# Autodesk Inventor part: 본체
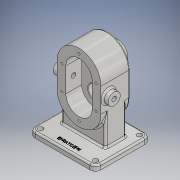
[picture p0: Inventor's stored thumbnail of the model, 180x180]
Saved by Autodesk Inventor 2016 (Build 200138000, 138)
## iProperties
Created: 2020-09
Part Number: 본체
Material: 알루미늄 6061
Document SubType Name: Modeling
Designer: WIN7
Density: 2.7 g/cm^3
Appearance: 알루미늄 - 평지
Mass: 1440.46 g
Surface Area: 785.636 cm^2
Volume: 533.505 cm^3
Author: WIN7
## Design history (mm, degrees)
sketch "스케치1"
  geometry: L1 (0, -62)-(0, -62); L2 (40, -22)-(40, 22); L3 (0, 62)-(0, 62); L4 (-40, 22)-(-40, -22); L5 (-40, -62)-(40, 62); L6 (40, -62)-(-40, 62); A1 r 40 centre (0, 22) between (0, 62) and (-40, 22); A2 r 40 centre (0, 22) between (40, 22) and (0, 62); A3 r 40 centre (0, -22) between (0, -62) and (40, -22); A4 r 40 centre (0, -22) between (-40, -22) and (0, -62); 1 further point
  constraints: 12 end point, 8 point on circle, 8 point on line, 8 tangent, 4 centre point, 3 equal radius, 2 midpoint, 2 parallel, 1 horizontal, 1 perpendicular
  dimensions: "d0" = 80 distance between parallel lines of L2 L4; "d1" = 124 distance between parallel lines of L3 L1; "d2" = 40 radius of A1
extrude "돌출1" new body sketch "스케치1" stored distance "d3" = 53; taper "d4" = 0 deg
sketch "스케치2"
  geometry: L1 (0, 46)-(0, 46); L2 (24, 22)-(24, -22); L3 (0, -46)-(0, -46); L4 (-24, -22)-(-24, 22); L5 (-24, 46)-(24, -46); L6 (24, 46)-(-24, -46); L7 (-40, 22)-(-40, -22) reference; A1 r 40 centre (0, 22) between (40, 22) and (-40, 22) reference; A2 r 24 centre (0, 22) between (0, 46) and (-24, 22); A3 r 24 centre (0, 22) between (24, 22) and (0, 46); A4 r 24 centre (0, -22) between (-24, -22) and (0, -46); A5 r 24 centre (0, -22) between (0, -46) and (24, -22); 6 further points
  constraints: 12 end point, 9 point on circle, 8 point on line, 8 tangent, 5 midpoint, 4 centre point, 3 equal radius, 2 parallel, 1 horizontal, 1 horizontal alignment, 1 perpendicular, 1 vertical alignment
  dimensions: "d5" = 92 distance of L6.start L5.end; "d6" = 48 distance between parallel lines of L2 L4; "d7" = 24 radius of A2
extrude "돌출2" cut sketch "스케치2" distance "d8" = 29; taper "d9" = 0 deg
node "작업 평면1"
sketch "스케치3"
  geometry: C1 r 12.5 at (0, 22); C2 r 12.5 at (0, -22); A1 r 24 centre (0, 22) between (24, 22) and (-24, 22) reference; A2 r 24 centre (0, -22) between (-24, -22) and (24, -22) reference; 1 further point
  constraints: 2 centre point, 2 coincident
  dimensions: "d11" = 25 diameter of C1; "d12" = 25 diameter of C2
extrude "돌출3" cut sketch "스케치3" distance "d13" = 15; taper "d14" = 0 deg
sketch "스케치4"
  geometry: L1 (22, -26.5)-(62, -26.5) reference; L2 (-22, -26.5)-(22, -26.5) reference; L3 (9.5, -17.5)-(34.5, -17.5) reference; L4 (22, -26.5)-(22, 26.5) reference; L5 (22, 26.5)-(22, -43.5); L6 (41, -26.5)-(41, -43.5); L7 (41, -43.5)-(36.404, -43.5); L8 (30.5, -17.5)-(30.5, -36.2); L9 (30.5, -36.2)-(36, -36.2); L10 (36, -36.2)-(36, -42.8); L11 (36, -42.8)-(36.404, -43.5); L12 (41, -26.5)-(30.5, -26.5); 1 further point
  constraints: 16 end point, 3 perpendicular, 3 point on line, 2 collinear, 2 vertical
  dimensions: "d19" = 38 diameter of L6 L5; "d20" = 17 distance between parallel lines of L1 L7; "d21" = 28 diameter of L10 L5; "d22" = 17 diameter of L8 L5; "d23" = 7.3 distance between parallel lines of L7 L9; "d24" = 30 deg angle of L10 L11; "d25" = 0.7 distance from line of L10.end L7
revolve "회전1" sketch "스케치4" stored, may be unused: angle "d26" = 90 deg
sketch "스케치5"
  geometry: C1 r 12.5 at (0, 0) reference; C2 r 8.5 at (0, 0); 1 further point
  constraints: 1 centre point, 1 coincident
extrude "돌출4" cut sketch "스케치5" stored distance "d27" = 15; taper "d28" = 0 deg
sketch "스케치6"
  geometry: L1 (60, 56.5)-(-60, 56.5); L2 (-60, 56.5)-(-60, -43.5); L3 (-60, -43.5)-(60, -43.5); L4 (60, -43.5)-(60, 56.5); L5 (-19, -43.5)-(19, -43.5) reference; L6 (-40, -26.5)-(40, -26.5) reference; 4 further points
  constraints: 8 end point, 4 midpoint, 2 parallel, 1 horizontal, 1 perpendicular, 1 vertical alignment
  dimensions: "d30" = 100 distance between parallel lines of L3 L1; "d31" = 120 distance between parallel lines of L2 L4
extrude "돌출5" join sketch "스케치6" distance "d32" = 10; taper "d33" = 0 deg
sketch "스케치7"
  geometry: L1 (-40, -18.5)-(40, -18.5); L2 (40, -18.5)-(40, 18.5); L3 (40, 18.5)-(-40, 18.5); L4 (-40, 18.5)-(-40, -18.5); L5 (60, 43.5)-(-60, 43.5) reference; 3 further points
  constraints: 8 end point, 2 midpoint, 2 parallel, 1 horizontal, 1 perpendicular, 1 vertical alignment
  dimensions: "d34" = 25 distance between parallel lines of L5 L3; "d35" = 37 distance between parallel lines of L1 L3; "d36" = 80 distance between parallel lines of L2 L4
extrude "돌출6" join sketch "스케치7" stored distance "d37" = 10; taper "d38" = 0 deg
sketch "스케치8"
  geometry: C1 r 12.5 at (0, -22) reference; A1 r 31 centre (0, 22) between (21.84, 0) and (-21.84, 0); A2 r 31 centre (0, -22) between (-21.84, 0) and (21.84, 0); A3 r 31 centre (0, -22) between (-5.188, 8.563) and (-21.84, 0); A4 r 31 centre (0, -22) between (21.84, 0) and (-5.188, 8.563); 8 further points
  constraints: 14 point on circle, 4 centre point, 2 coincident, 2 other
  dimensions: "d39" = 62 diameter of A1; "d40" = 62 diameter of A2
hole "구멍1" sketch "스케치8" at (-31, 22), (0, 53), (31, 22), (-31, -22), (31, -22), (0, -53) diameter "d41" = 4.134; stored, may be unused: countersink angle "d45" = 90 deg, drill point angle "d47" = 118 deg; dims "d42" = 10, "d43" = 4, "d44" = 2, "d46" = 12
sketch "스케치9"
  geometry: L1 (0, 0)-(0, 44) reference; L2 (-30, -68)-(70, -68) reference; C1 r 11 at (14, 22); 1 further point
  constraints: 1 centre point
  dimensions: "d49" = 22 diameter of C1; "d50" = 14 distance from line of C1.centre L1; "d52" = 90 distance from line of C1.centre L2
extrude "돌출7" join sketch "스케치9" distance "d53" = 10; taper "d54" = 0 deg
hole "구멍2" diameter "d57" = 8.376; stored, may be unused: countersink angle "d61" = 90 deg, drill point angle "d63" = 118 deg; dims "d55" = 10, "d56" = 10, "d58" = 20, "d59" = 4, "d60" = 2, "d62" = 10
fillet "모깎기1" dims "d64" = 10
sketch "스케치10"
  geometry: C1 r 4.5 at (-50, -46.5); C2 r 4.5 at (50, -46.5); C3 r 4.5 at (-50, 33.5); C4 r 4.5 at (50, 33.5); A1 r 10 centre (-50, -46.5) between (-60, -46.5) and (-50, -56.5) reference; A2 r 10 centre (50, -46.5) between (50, -56.5) and (60, -46.5) reference; A3 r 10 centre (-50, 33.5) between (-50, 43.5) and (-60, 33.5) reference; A4 r 10 centre (50, 33.5) between (60, 33.5) and (50, 43.5) reference; 1 further point
  constraints: 4 centre point, 4 coincident
  dimensions: "d65" = 9 diameter of C1; "d66" = 9 diameter of C2; "d67" = 9 diameter of C3; "d68" = 9 diameter of C4
extrude "돌출8" cut sketch "스케치10" stored distance "d69" = 10; taper "d70" = 0 deg
fillet "모깎기2" dims "d71" = 3
fillet "모깎기3" dims "d72" = 3
fillet "모깎기4" dims "d73" = 3
node "작업 평면3"
sketch "스케치11"
  geometry: L1 (-60, 33.5)-(-60, -46.5) reference; L2 (-50, -56.5)-(50, -56.5) reference; 2 further points
  constraints: 1 other
  dimensions: "d76" = 60 distance from line of point (0, -44.5) L1; "d77" = 12 distance from line of point (0, -44.5) L2
feature "엠보싱1" sketch "스케치11" dims "d0" = 80, "d1" = 124, "d2" = 40, "d5" = 92, "d6" = 48, "d7" = 24, "d78" = 0.5, "d79" = 0
fillet "모깎기5" dims "d80" = 0.5
chamfer "모따기1" distance "d81" = 1; stored, may be unused: second distance "d82" = 2, angle "d83" = 45 deg
chamfer "모따기2" distance "d84" = 1; stored, may be unused: second distance "d85" = 2, angle "d86" = 45 deg
node "솔리드1"
mirror "대칭1"
other parameters: "d75" = 0.5
